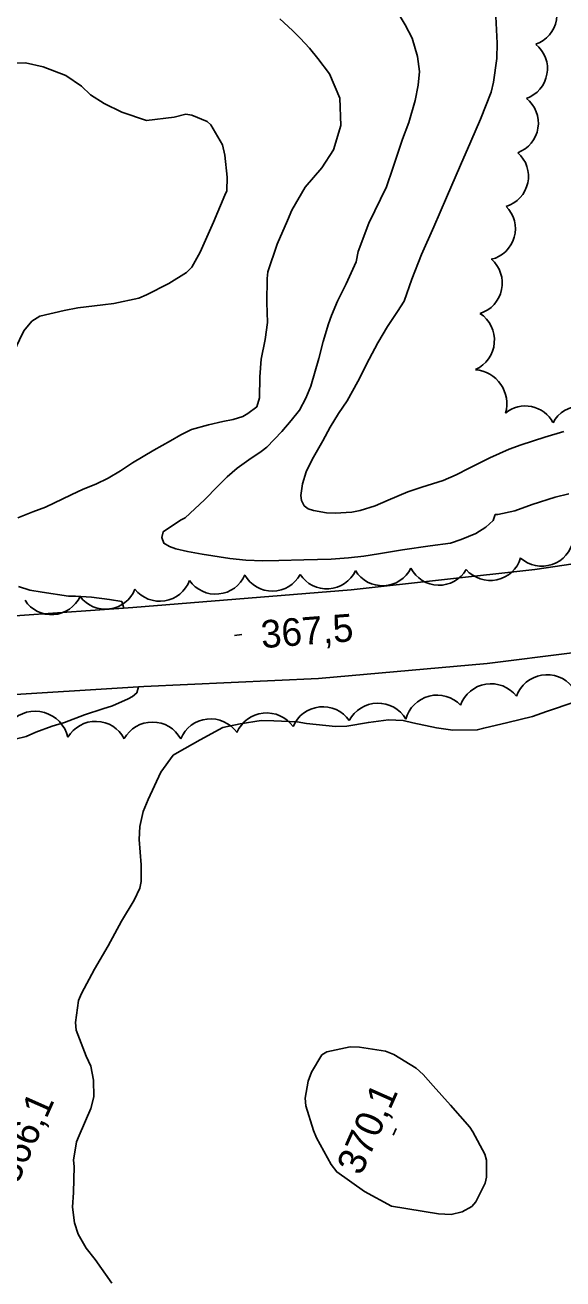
# Model space of a CAD drawing. Extents: x 287698 to 290158, y 5234163 to 5237182.
# Drawn here: x 288304 to 288362.3, y 5235484.4 to 5235620.4 of the extents above; entities that cross this region are included whole.
import ezdxf

# ---------------------------------------------------------------- set-up
doc = ezdxf.new("R2010")
doc.units = 0
for name, color, linetype in [('Niveau 1', 7, 'Continuous'), ('Niveau 2', 7, 'Continuous'), ('Niveau 21', 7, 'Continuous'), ('Niveau 3', 7, 'Continuous'), ('Niveau 44', 7, 'Continuous')]:
    doc.layers.add(name, color=color, linetype=linetype)

msp = doc.modelspace()

# ---------------------------------------------------------------- linework, layer by layer
at = {"layer": 'Niveau 1'}
for points in [[(288302.33, 5235616.26), (288304.01, 5235616.3), (288305.95, 5235615.84), (288308.38, 5235614.93), (288310.09, 5235613.75), (288311.07, 5235612.81), (288312.54, 5235611.87), (288314.48, 5235610.95), (288317.15, 5235610.04), (288320.14, 5235610.41), (288321.43, 5235610.71), (288322.05, 5235610.63), (288323.71, 5235609.91), (288324.12, 5235609.55), (288325.38, 5235607.41)], [(288325.38, 5235607.41), (288325.64, 5235606.28), (288325.88, 5235603.87), (288325.85, 5235602.39), (288325.65, 5235601.92), (288324.4, 5235598.99), (288322.96, 5235595.77), (288322.05, 5235594.13), (288321.49, 5235593.53), (288319.56, 5235592.34), (288317.16, 5235591.11), (288316.3, 5235590.78), (288313.59, 5235590.17), (288312.39, 5235590.03), (288309.7, 5235589.72), (288308.21, 5235589.42), (288305.56, 5235588.82), (288304.72, 5235588.26), (288303.85, 5235587.23), (288303.35, 5235586.25), (288302.28, 5235583.93)], [(288343.72, 5235492.26), (288340.79, 5235493.88), (288337.78, 5235495.98), (288337.18, 5235496.78), (288335.58, 5235499.7), (288335.26, 5235500.49), (288334.44, 5235503.16), (288334.36, 5235503.99), (288334.69, 5235505.82), (288335.04, 5235506.79), (288336.17, 5235508.68), (288336.71, 5235509), (288339.23, 5235509.55), (288340.27, 5235509.52), (288343.09, 5235509.09), (288343.99, 5235508.73), (288346.41, 5235507.24), (288347.18, 5235506.57), (288348.26, 5235505.31), (288350.14, 5235503.23), (288352.22, 5235500.83), (288352.56, 5235500.32), (288353.85, 5235497.91), (288354.03, 5235497.26), (288354.05, 5235495.41), (288353.9, 5235494.78), (288352.89, 5235492.75), (288352.44, 5235492.25), (288351.38, 5235491.65), (288350.2, 5235491.38), (288348.82, 5235491.45), (288343.72, 5235492.26)]]:
    msp.add_lwpolyline(points, dxfattribs=at)
at = {"layer": 'Niveau 2'}
for points in [[(288336.97, 5235631.48), (288338.56, 5235630.47), (288339.66, 5235629.47), (288340.87, 5235627.89), (288342.2, 5235625.89), (288343.52, 5235623.55), (288344.15, 5235622.14), (288345.21, 5235620.41), (288345.97, 5235618.96), (288346.56, 5235616.97), (288346.77, 5235615.34), (288346.62, 5235613.87), (288346.28, 5235612.22), (288345.6, 5235609.83), (288344.91, 5235608), (288343.87, 5235604.88), (288343.18, 5235602.85), (288341.25, 5235598.89)], [(288345.95, 5235592.81), (288346.99, 5235595.49), (288348.31, 5235598.5), (288349.69, 5235601.67), (288351.2, 5235605.2), (288352.33, 5235607.75), (288353.39, 5235610.19), (288354.55, 5235613.09), (288354.81, 5235614.19), (288355.14, 5235616.76), (288355.18, 5235618.43), (288355.05, 5235621.3), (288355.24, 5235623.62), (288355.42, 5235624.27), (288355.6, 5235625)], [(288331.62, 5235621.05), (288333, 5235619.8), (288333.81, 5235618.95), (288334.84, 5235617.87), (288335.73, 5235616.75), (288336.99, 5235615.11), (288338.13, 5235612.46), (288338.23, 5235609.48), (288337.45, 5235606.85), (288336.16, 5235604.91)], [(288336.16, 5235604.91), (288334.37, 5235602.8), (288332.92, 5235600.32), (288332.43, 5235599.19), (288331.33, 5235596.62), (288330.32, 5235593.62), (288330.24, 5235592.9), (288330.19, 5235590.28), (288330.26, 5235588.11), (288330.02, 5235586.29), (288329.57, 5235584.15), (288329.43, 5235582.22), (288329.4, 5235579.96), (288329.12, 5235578.99)], [(288341.25, 5235598.89), (288340.1, 5235595.82), (288339.89, 5235594.69)], [(288339.89, 5235594.69), (288338.8, 5235592.3), (288337.88, 5235590.42), (288337.2, 5235588.89), (288336.89, 5235587.98), (288336.32, 5235586.07), (288335.83, 5235584.21), (288334.97, 5235581.21), (288334.43, 5235579.91), (288333.75, 5235578.63), (288332.85, 5235577.48), (288331.84, 5235576.31), (288330.21, 5235574.61), (288329.58, 5235574.13), (288328.23, 5235573.24), (288326.97, 5235572.34), (288325.89, 5235571.4), (288324.9, 5235570.36), (288323.42, 5235568.88), (288321.35, 5235566.94), (288320.85, 5235566.67), (288318.97, 5235565.42), (288318.8, 5235564.82), (288319.04, 5235564.17), (288319.64, 5235563.81), (288320.31, 5235563.57), (288321.61, 5235563.28), (288323.2, 5235562.99), (288326.2, 5235562.52), (288327.93, 5235562.35), (288329.75, 5235562.26), (288331.51, 5235562.29), (288334.23, 5235562.37), (288337.19, 5235562.47), (288339.07, 5235562.6), (288340.73, 5235562.77), (288342.3, 5235563.02), (288344.93, 5235563.46), (288347.93, 5235563.91), (288350.12, 5235564.2), (288351.28, 5235564.59), (288352.89, 5235565.22), (288353.97, 5235565.93), (288354.77, 5235566.63), (288354.98, 5235567.28), (288354.98, 5235567.28)], [(288345.95, 5235592.81), (288345.09, 5235590.44), (288344.37, 5235589.3), (288343.3, 5235587.69), (288342.25, 5235585.91), (288341.31, 5235584.16), (288340.06, 5235581.73), (288338.92, 5235579.63), (288337.97, 5235578.25), (288337.08, 5235576.76), (288336.28, 5235575.29), (288335.13, 5235573.28), (288334.46, 5235571.93), (288334.06, 5235570.64), (288333.88, 5235569.36), (288333.96, 5235568.82), (288334.26, 5235568.24), (288334.68, 5235567.91), (288335.28, 5235567.72), (288336.67, 5235567.49), (288337.6, 5235567.43), (288339.42, 5235567.55), (288340.31, 5235567.73), (288341.95, 5235568.22), (288343.36, 5235568.85), (288345.51, 5235569.75), (288347.03, 5235570.28), (288349.35, 5235571), (288350.74, 5235571.61), (288352.16, 5235572.32), (288354.4, 5235573.45), (288356.49, 5235574.4), (288357.81, 5235574.86), (288360.36, 5235575.7), (288362.43, 5235576.31)], [(288329.12, 5235578.99), (288328.15, 5235578.26), (288327.61, 5235577.94), (288326.55, 5235577.59), (288325.44, 5235577.39), (288323.87, 5235577.03), (288322.04, 5235576.5), (288320.87, 5235575.95), (288319.74, 5235575.27), (288317.94, 5235574.28), (288315.64, 5235572.9), (288314.33, 5235572.03), (288312.98, 5235571.23), (288311.63, 5235570.6), (288310.26, 5235570.06), (288308.98, 5235569.42), (288306.19, 5235568.09), (288304.8, 5235567.59), (288303.17, 5235566.92)], [(288354.98, 5235567.28), (288355.26, 5235567.29), (288357.09, 5235567.68), (288358.98, 5235568.37), (288361.49, 5235569.19), (288362.96, 5235569.54)], [(288303.24, 5235559.48), (288304.5, 5235559.1), (288305.83, 5235558.87), (288308.69, 5235558.43), (288309.45, 5235558.43), (288311.17, 5235558.32), (288313.12, 5235558.09), (288314.46, 5235557.85)], [(288314.46, 5235557.85), (288314.67, 5235557.15)], [(288316.26, 5235548.59), (288316.11, 5235547.96), (288315.62, 5235547.55), (288315.14, 5235547.3), (288313.46, 5235546.53), (288312.42, 5235546.21), (288310.43, 5235545.55), (288308.23, 5235544.74), (288306.92, 5235544.32), (288305.13, 5235543.69), (288304.09, 5235543.22), (288302.88, 5235542.94), (288301.55, 5235542.7), (288300.33, 5235542.32), (288299.34, 5235541.91), (288298.18, 5235541.59), (288296.99, 5235541.64), (288296.58, 5235541.94)], [(288320.03, 5235541.19), (288320.47, 5235541.45), (288322.97, 5235542.86), (288325.44, 5235544.19), (288327.29, 5235544.59), (288329.59, 5235544.95), (288330.95, 5235544.93), (288333.48, 5235544.8), (288334.51, 5235544.62), (288337.65, 5235544.3), (288338.87, 5235544.33), (288341.22, 5235544.74), (288343.39, 5235545.01), (288344.98, 5235544.96), (288346.03, 5235544.71), (288348.6, 5235544.17), (288350.39, 5235543.92), (288353.03, 5235543.93), (288353.74, 5235544.13), (288356.36, 5235544.75), (288359.03, 5235545.4), (288360.53, 5235545.93), (288363.67, 5235546.98)], [(288313.37, 5235483.93), (288311.57, 5235486.48), (288310.59, 5235487.71), (288309.74, 5235489.24), (288309.35, 5235490.46), (288309.11, 5235492.18), (288309.21, 5235493.75), (288309.31, 5235496.59), (288309.21, 5235497.26), (288309.54, 5235499.24), (288309.83, 5235499.92), (288311.09, 5235502.87), (288311.44, 5235504.14), (288311.41, 5235505.95), (288311.1, 5235507.44), (288310.6, 5235508.55), (288309.52, 5235511.37), (288309.43, 5235512.21), (288309.77, 5235514.57), (288310.09, 5235515.35), (288311.51, 5235517.99), (288312.97, 5235520.52), (288314.42, 5235523.18), (288315.79, 5235525.48), (288316.42, 5235526.76), (288316.57, 5235527.5), (288316.56, 5235529.28), (288316.35, 5235532.04), (288316.42, 5235533.47), (288316.78, 5235535.07), (288317.31, 5235536.4), (288318.69, 5235539.34), (288320.03, 5235541.19)]]:
    msp.add_lwpolyline(points, dxfattribs=at)
at = {"layer": 'Niveau 21'}
for points in [[(288412.58, 5235574.13), (288396.62, 5235568.2), (288378.32, 5235564.14), (288359.27, 5235561.33), (288339.36, 5235559.13), (288315.66, 5235557.22), (288295.2, 5235555.75), (288278, 5235554.48), (288263.36, 5235553.19), (288246.09, 5235550.65), (288233.2, 5235547.93), (288218.94, 5235544.37), (288206.85, 5235539.96), (288196.69, 5235533.87), (288187.01, 5235526.21), (288177.75, 5235515.57), (288171.84, 5235507.18), (288164.1, 5235494.63), (288155.28, 5235480.18), (288145.74, 5235463.07)], [(288404.36, 5235561.32), (288386.9, 5235556.35), (288372.55, 5235553.45), (288354.12, 5235551.14), (288335.81, 5235549.51), (288316.85, 5235548.63), (288300.02, 5235547.58), (288283.18, 5235546.56), (288266.22, 5235544.18), (288249.42, 5235540.87), (288230.59, 5235536.58), (288216.96, 5235532.39), (288205.61, 5235526.76), (288196.13, 5235519.89), (288186.88, 5235510.49), (288178.12, 5235498.91), (288170.26, 5235485.52), (288162.7, 5235472.69), (288155.23, 5235459.52)]]:
    msp.add_lwpolyline(points, dxfattribs=at)
at = {"layer": 'Niveau 3'}
for p, q in [((288326.69, 5235554.19), (288327.48, 5235554.27)), ((288343.92, 5235499.96), (288344.24, 5235500.69))]:
    msp.add_line(p, q, dxfattribs=at)
at = {"layer": 'Niveau 44'}
for centre, radius, start, end in [((288352.51, 5235579.29), 3.73, 344.614, 84.8693), ((288360.59, 5235546.4), 3.52, 38.5221, 160.2185), ((288354.52, 5235545.43), 3.51, 38.0697, 160.1182)]:
    msp.add_arc(centre, radius, start, end, dxfattribs=at)
for centre, major_axis, ratio, start_param, end_param in [((288358.26, 5235621.53), (3.37, -0.59), 0.999978, 5.220954, 7.342977), ((288357.23, 5235615.65), (3.37, -0.58), 0.998377, 5.218241, 7.339495), ((288356.23, 5235609.75), (3.39, -0.52), 0.996505, 5.218604, 7.33529), ((288355.17, 5235603.98), (3.35, -0.7), 0.997027, 5.216916, 7.340174), ((288353.75, 5235598.3), (3.25, -1.07), 0.998076, 5.267934, 7.387425), ((288352.31, 5235592.39), (3.36, -0.71), 0.999644, 5.222398, 7.347905), ((288351.39, 5235586.2), (3.44, -0.66), 0.999696, 5.330222, 7.457137), ((288358.25, 5235575.68), (-2.96, -1.65), 0.999994, 3.117949, 4.890706), ((288364.24, 5235575.66), (-3.39, 0), 0.99961, 3.63271, 5.792068), ((288360.05, 5235565.13), (1.11, -3.26), 0.999801, 5.2187, 7.344619), ((288342.75, 5235563.01), (0.16, -3.44), 0.99995, 5.217129, 7.346381), ((288348.88, 5235563.07), (-0.09, -3.44), 0.99995, 5.217447, 7.346528), ((288354.44, 5235563.58), (0.72, -3.37), 0.999951, 5.218451, 7.349671), ((288318.59, 5235561.33), (0.54, -3.4), 0.999202, 5.22302, 7.344267), ((288324.65, 5235562.1), (0, -3.44), 0.999597, 5.317224, 7.44675), ((288330.8, 5235562.44), (-0.23, -3.44), 0.999386, 5.299895, 7.423168), ((288336.71, 5235562.68), (0.23, -3.44), 0.999912, 5.22055, 7.342804), ((288312.69, 5235560.48), (0.48, -3.42), 0.996548, 5.21691, 7.334536), ((288306.84, 5235559.87), (0.26, -3.43), 0.996799, 5.213796, 7.339978), ((288348.68, 5235544.2), (-2.49, -2.47), 0.999995, 3.120629, 5.243158), ((288336.28, 5235542.92), (-0.25, 3.51), 0.997977, 5.258913, 7.3823), ((288342.26, 5235543.31), (-0.09, 3.52), 0.999995, 5.221039, 7.344252), ((288305.06, 5235542.31), (1, 3.51), 0.999956, 5.218665, 7.347405), ((288324.1, 5235541.61), (0.45, 3.49), 0.999931, 5.460284, 7.583108), ((288330.18, 5235542.27), (-0.16, 3.5), 0.999026, 5.279852, 7.404615), ((288311.63, 5235541.35), (0.24, 3.5), 0.998175, 5.263343, 7.386888), ((288317.79, 5235541.28), (0.01, 3.5), 0.999979, 5.219895, 7.348753)]:
    msp.add_ellipse(centre, major_axis=major_axis, ratio=ratio, start_param=start_param, end_param=end_param, dxfattribs=at)

# ---------------------------------------------------------------- texts
at = {"layer": 'Niveau 3'}
for s, rotation, p in [('367,5', 4.434, (288329.67, 5235552.79)), ('370,1', 66.1217, (288340.42, 5235495.49)), ('366,1', 66.1217, (288303.13, 5235494.53))]:
    msp.add_text(s, height=3, rotation=rotation, dxfattribs=at).set_placement(p)

doc.saveas('drawing.dxf')
